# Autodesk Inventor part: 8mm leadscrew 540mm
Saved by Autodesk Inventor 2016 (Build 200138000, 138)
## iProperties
Created: 2015-11
Part Number: 8mm leadscrew 540mm
Material: Generic
Document SubType Name: Modeling
Designer: John
Density: 1 g/cm^3
Appearance: Default
Author: John
Revision Number: ANY
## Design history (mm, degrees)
feature "Boss-Extrude1"
body "Solid1"
